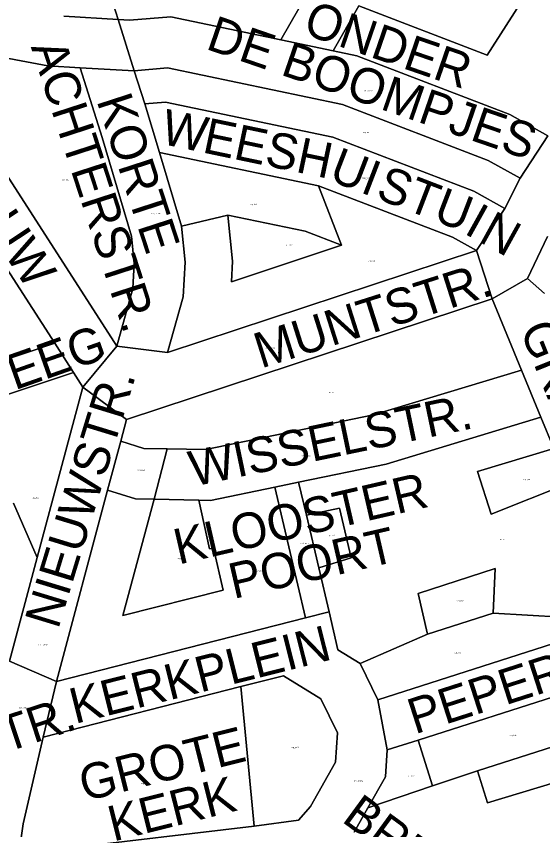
# Model space of a CAD drawing. Extents: x 14356 to 207184, y 3423 to 537581.
# Drawn here: x 132830.2 to 132986, y 517028.5 to 517269.3 of the extents above; entities that cross this region are included whole.
import ezdxf

# ---------------------------------------------------------------- set-up
doc = ezdxf.new("R2010")
doc.units = 0
for name, color, linetype in [('GEOCAD IKB VLAK TEKST CLASSIFICATIE', 7, 'Continuous'), ('PLATTEGROND ACHTERGROND BEBOUW', 7, 'Continuous'), ('PLATTEGROND ACHTERGROND GROEN', 7, 'Continuous'), ('PLATTEGROND BEBOUWING', 7, 'Continuous'), ('PLATTEGROND ERFTOEGANGSWEG', 7, 'Continuous'), ('PLATTEGROND GEB ONTSL WEG E', 7, 'Continuous'), ('PLATTEGROND HULPLIJN', 7, 'Continuous'), ('PLATTEGROND LIJN', 7, 'Continuous'), ('PLATTEGROND NAAM ERFTOEGANGSWEG', 7, 'Continuous'), ('PLATTEGROND NAAM GEB ONTSL WEG E', 7, 'Continuous'), ('PLATTEGROND VOET FIETSPAD', 7, 'Continuous'), ('PLATTEGROND WATER', 7, 'Continuous')]:
    doc.layers.add(name, color=color, linetype=linetype)

msp = doc.modelspace()

# ---------------------------------------------------------------- linework, layer by layer
at = {"layer": 'PLATTEGROND ACHTERGROND BEBOUW'}
for p, q in [((132871, 517126.31), (132884.25, 517126.05)), ((132919.7, 517106.06), (132916.05, 517121.64)), ((132971.37, 517092.61), (132951.93, 517086.38)), ((132966.69, 517045.96), (133006.29, 517058.64)), ((132939.97, 517052.1), (132949.17, 517055.05)), ((132949.17, 517055.05), (132953.43, 517041.45)), ((132953.43, 517041.45), (132934.29, 517034.94))]:
    msp.add_line(p, q, dxfattribs=at)
for points in [[(132930.4, 517308.13), (132983.31, 517279.35), (132969.62, 517257.76), (132931.54, 517272.41)], [(132926.49, 517201.5), (132893.87, 517190.73), (132894.2, 517196.86), (132892.81, 517210.43)], [(132892.81, 517210.43), (132915.69, 517205.65), (132926.49, 517201.5)], [(132993.54, 517130.99), (132970.76, 517121.87), (132966.74, 517134.52), (132989.27, 517141.37)], [(132884.25, 517126.05), (132887.35, 517111.62), (132888.55, 517111.87), (132891.46, 517099.46), (132861.78, 517091.89), (132871, 517126.31)], [(132916.05, 517121.64), (132925.85, 517123.67), (132929.3, 517108.94), (132919.7, 517106.06)], [(132951.93, 517086.38), (132949.11, 517098.39), (132971.89, 517105.87), (132971.37, 517092.61)], [(133006.29, 517058.64), (133009.49, 517048.51), (132969.65, 517036.5), (132966.69, 517045.96)], [(132934.29, 517034.94), (132939.45, 517044.13), (132939.97, 517052.1)]]:
    msp.add_lwpolyline(points, dxfattribs=at)
at = {"layer": 'PLATTEGROND ACHTERGROND GROEN'}
msp.add_line((132900.63, 517029.52), (132896.62, 517070.85), dxfattribs=at)
msp.add_lwpolyline([(132896.62, 517070.85), (132909.29, 517074.08), (132920.37, 517067.21), (132925.27, 517057.2), (132924.7, 517048.51), (132917.3, 517035.33), (132913.75, 517031.29), (132900.63, 517029.52)], dxfattribs=at)
at = {"layer": 'PLATTEGROND BEBOUWING'}
for p, q in [((132860.33, 517268.33), (132824.26, 517381.98)), ((132923.95, 517259.09), (132931.54, 517272.41)), ((132781.81, 517265.46), (132841.56, 517172.49)), ((132859.92, 517171.66), (132802.1, 517261.65)), ((132879.07, 517207.16), (132872.61, 517228.96)), ((132872.61, 517228.96), (132919.66, 517219.12)), ((132919.66, 517219.12), (132926.49, 517201.5)), ((132926.49, 517201.5), (132919.66, 517219.12)), ((132892.81, 517210.43), (132879.07, 517207.16)), ((132879.07, 517207.16), (132892.81, 517210.43)), ((132966.42, 517199.93), (132874.97, 517169.75)), ((132862.84, 517149.95), (132971.03, 517185.66)), ((132971.03, 517185.66), (132979.7, 517164.59)), ((132841.56, 517172.49), (132735.25, 517137.19)), ((132792.94, 517145.81), (132847.14, 517163.81)), ((132847.14, 517163.81), (132849.88, 517159.54)), ((132849.88, 517159.54), (132836.36, 517109.07)), ((132985.44, 517150.66), (132989.27, 517141.37)), ((132861.11, 517143.49), (132862.84, 517149.95)), ((132916.05, 517121.64), (132913.77, 517131.38)), ((132842.07, 517072.41), (132857.23, 517128.99)), ((132906.73, 517129.92), (132915.8, 517091.23)), ((132829.41, 517125.12), (132836.36, 517109.07)), ((132836.36, 517109.07), (132829.41, 517125.12)), ((132836.36, 517109.07), (132828.15, 517078.41)), ((132922.76, 517093), (132919.7, 517106.06)), ((132915.8, 517091.23), (132842.07, 517072.41)), ((133010.27, 517090.37), (132937.19, 517066.96)), ((132951.93, 517086.38), (132971.37, 517092.61)), ((133010.27, 517090.37), (132971.37, 517092.61)), ((132971.37, 517092.61), (133010.27, 517090.37)), ((132951.93, 517086.38), (132931.94, 517077.68)), ((132931.94, 517077.68), (132951.93, 517086.38)), ((132937.19, 517066.96), (132931.94, 517077.68)), ((132949.17, 517055.05), (133015.4, 517076.27)), ((132838.11, 517055.92), (132896.62, 517070.85)), ((132896.62, 517070.85), (132900.63, 517029.52)), ((133006.29, 517058.64), (132966.69, 517045.96)), ((132953.43, 517041.45), (132949.17, 517055.05)), ((132953.43, 517041.45), (132966.69, 517045.96)), ((132966.69, 517045.96), (132953.43, 517041.45)), ((132934.29, 517034.94), (132953.43, 517041.45)), ((132930.24, 517027.72), (132934.29, 517034.94)), ((132900.63, 517029.52), (132830.98, 517021.38))]:
    msp.add_line(p, q, dxfattribs=at)
for points in [[(132931.54, 517272.41), (132969.62, 517257.76), (132983.31, 517279.35), (132930.4, 517308.13)], [(132874.3, 517305.44), (132881.2, 517278.25), (132885.43, 517277.36), (132920.89, 517286.83), (132921.43, 517284.95), (132908.52, 517262.32)], [(132908.52, 517262.32), (132875.92, 517269.13), (132863.72, 517268.12), (132860.33, 517268.33)], [(132802.1, 517261.65), (132839.56, 517254.6), (132849.13, 517254)], [(132987.56, 517233.95), (132976.25, 517240.21), (132931.01, 517257.62), (132923.95, 517259.09)], [(132849.13, 517254), (132855.64, 517233.44), (132864.29, 517204.24), (132865.12, 517196.16), (132864.72, 517188.68), (132859.92, 517171.66)], [(132919.66, 517219.12), (132959.3, 517203.88), (132966.42, 517199.93)], [(132926.49, 517201.5), (132915.69, 517205.65), (132892.81, 517210.43)], [(132892.81, 517210.43), (132894.2, 517196.86), (132893.87, 517190.73), (132926.49, 517201.5)], [(132874.97, 517169.75), (132879.61, 517186.22), (132880.16, 517196.52), (132879.07, 517207.16)], [(132979.7, 517164.59), (132935.97, 517151.3), (132886.29, 517141.01), (132874.84, 517141.24)], [(132913.77, 517131.38), (132939.68, 517136.75), (132985.44, 517150.66)], [(132874.84, 517141.24), (132867.93, 517141.37), (132861.11, 517143.49)], [(132989.27, 517141.37), (132966.74, 517134.52), (132970.76, 517121.87), (132993.54, 517130.99)], [(132857.23, 517128.99), (132865.51, 517126.42), (132871, 517126.31)], [(132884.25, 517126.05), (132887.68, 517125.98), (132906.73, 517129.92)], [(132871, 517126.31), (132861.78, 517091.89), (132891.46, 517099.46), (132888.55, 517111.87), (132887.35, 517111.62), (132884.25, 517126.05)], [(132919.7, 517106.06), (132929.3, 517108.94), (132925.85, 517123.67), (132916.05, 517121.64)], [(132971.37, 517092.61), (132971.89, 517105.87), (132949.11, 517098.39), (132951.93, 517086.38)], [(132931.94, 517077.68), (132925.4, 517081.74), (132922.76, 517093)], [(132966.69, 517045.96), (132969.65, 517036.5), (133009.49, 517048.51), (133006.29, 517058.64)], [(132830.98, 517021.38), (132832.25, 517030.21), (132838.11, 517055.92)]]:
    msp.add_lwpolyline(points, dxfattribs=at)
at = {"layer": 'PLATTEGROND ERFTOEGANGSWEG'}
for p, q in [((132824.26, 517381.98), (132860.33, 517268.33)), ((132931.54, 517272.41), (132923.95, 517259.09)), ((132860.33, 517268.33), (132844.27, 517269.33)), ((132923.95, 517259.09), (132908.52, 517262.32)), ((132849.13, 517254), (132865.12, 517253.18)), ((132865.12, 517253.18), (132868.21, 517243.41)), ((132868.21, 517243.41), (132872.61, 517228.96)), ((132872.61, 517228.96), (132879.07, 517207.16)), ((132981.49, 517191.7), (132987.41, 517204.13)), ((132971.03, 517185.66), (132981.49, 517191.7)), ((132981.49, 517191.7), (132986.59, 517187.25)), ((132986.59, 517187.25), (132981.49, 517191.7)), ((132979.7, 517164.59), (132971.03, 517185.66)), ((132874.97, 517169.75), (132859.92, 517171.66)), ((132985.44, 517150.66), (132979.7, 517164.59)), ((132979.7, 517164.59), (132985.44, 517150.66)), ((132989.27, 517141.37), (132985.44, 517150.66)), ((132871, 517126.31), (132874.84, 517141.24)), ((132913.77, 517131.38), (132906.73, 517129.92)), ((132884.25, 517126.05), (132871, 517126.31)), ((132915.8, 517091.23), (132922.76, 517093)), ((132842.07, 517072.41), (132915.8, 517091.23)), ((132931.94, 517077.68), (132937.19, 517066.96)), ((132838.11, 517055.92), (132842.07, 517072.41)), ((132896.62, 517070.85), (132838.11, 517055.92)), ((132937.19, 517066.96), (132939.97, 517052.1)), ((132934.29, 517034.94), (132930.24, 517027.72)), ((132830.98, 517021.38), (132900.63, 517029.52))]:
    msp.add_line(p, q, dxfattribs=at)
for points in [[(132908.52, 517262.32), (132921.43, 517284.95), (132920.89, 517286.83), (132885.43, 517277.36), (132881.2, 517278.25), (132874.3, 517305.44)], [(132859.92, 517171.66), (132864.72, 517188.68), (132865.12, 517196.16), (132864.29, 517204.24), (132855.64, 517233.44), (132849.13, 517254)], [(132879.07, 517207.16), (132880.16, 517196.52), (132879.61, 517186.22), (132874.97, 517169.75)], [(132874.84, 517141.24), (132886.29, 517141.01), (132935.97, 517151.3), (132979.7, 517164.59)], [(132985.44, 517150.66), (132939.68, 517136.75), (132913.77, 517131.38)], [(132906.73, 517129.92), (132887.68, 517125.98), (132884.25, 517126.05)], [(132922.76, 517093), (132925.4, 517081.74), (132931.94, 517077.68)], [(132900.63, 517029.52), (132913.75, 517031.29), (132917.3, 517035.33), (132924.7, 517048.51), (132925.27, 517057.2), (132920.37, 517067.21), (132909.29, 517074.08), (132896.62, 517070.85)], [(132939.97, 517052.1), (132939.45, 517044.13), (132934.29, 517034.94)]]:
    msp.add_lwpolyline(points, dxfattribs=at)
at = {"layer": 'PLATTEGROND GEB ONTSL WEG E'}
for p, q in [((132844.27, 517269.33), (132860.33, 517268.33)), ((132865.12, 517253.18), (132860.33, 517268.33)), ((132860.33, 517268.33), (132865.12, 517253.18)), ((132841.56, 517172.49), (132781.81, 517265.46)), ((132802.1, 517261.65), (132859.92, 517171.66)), ((132908.52, 517262.32), (132923.95, 517259.09)), ((132865.12, 517253.18), (132849.13, 517254)), ((132979.34, 517221.36), (132987.56, 517233.95)), ((132987.56, 517233.95), (132979.34, 517221.36)), ((132974.8, 517212.44), (132979.34, 517221.36)), ((132966.42, 517199.93), (132974.8, 517212.44)), ((132987.41, 517204.13), (132981.49, 517191.7)), ((132874.97, 517169.75), (132966.42, 517199.93)), ((132971.03, 517185.66), (132966.42, 517199.93)), ((132966.42, 517199.93), (132971.03, 517185.66)), ((132981.49, 517191.7), (132971.03, 517185.66)), ((132971.03, 517185.66), (132862.84, 517149.95)), ((132847.14, 517163.81), (132841.56, 517172.49)), ((132859.92, 517171.66), (132849.88, 517159.54)), ((132849.88, 517159.54), (132859.92, 517171.66)), ((132859.92, 517171.66), (132874.97, 517169.75)), ((132849.88, 517159.54), (132847.14, 517163.81)), ((132836.36, 517109.07), (132849.88, 517159.54)), ((132849.88, 517159.54), (132862.84, 517149.95)), ((132862.84, 517149.95), (132849.88, 517159.54)), ((132862.84, 517149.95), (132861.11, 517143.49)), ((132861.11, 517143.49), (132857.23, 517128.99)), ((132857.23, 517128.99), (132842.07, 517072.41)), ((132828.15, 517078.41), (132836.36, 517109.07)), ((132828.15, 517078.41), (132842.07, 517072.41)), ((132842.07, 517072.41), (132828.15, 517078.41)), ((132842.07, 517072.41), (132838.11, 517055.92))]:
    msp.add_line(p, q, dxfattribs=at)
for points in [[(132860.33, 517268.33), (132863.72, 517268.12), (132875.92, 517269.13), (132908.52, 517262.32)], [(132849.13, 517254), (132839.56, 517254.6), (132802.1, 517261.65)], [(132923.95, 517259.09), (132931.01, 517257.62), (132976.25, 517240.21), (132987.56, 517233.95)], [(132979.34, 517221.36), (132969.89, 517226.59), (132926.75, 517243.18), (132874.99, 517254), (132865.12, 517253.18)], [(132838.11, 517055.92), (132832.25, 517030.21), (132830.98, 517021.38)]]:
    msp.add_lwpolyline(points, dxfattribs=at)
at = {"layer": 'PLATTEGROND HULPLIJN'}
for p, q in [((132860.33, 517268.33), (132844.27, 517269.33)), ((132865.12, 517253.18), (132860.33, 517268.33)), ((132923.95, 517259.09), (132908.52, 517262.32)), ((132849.13, 517254), (132865.12, 517253.18)), ((132872.61, 517228.96), (132868.21, 517243.41)), ((132979.34, 517221.36), (132987.56, 517233.95)), ((132926.49, 517201.5), (132919.66, 517219.12)), ((132974.8, 517212.44), (132966.42, 517199.93)), ((132892.81, 517210.43), (132879.07, 517207.16)), ((132981.49, 517191.7), (132987.41, 517204.13)), ((132966.42, 517199.93), (132971.03, 517185.66)), ((132971.03, 517185.66), (132981.49, 517191.7)), ((132981.49, 517191.7), (132986.59, 517187.25)), ((132847.14, 517163.81), (132841.56, 517172.49)), ((132849.88, 517159.54), (132859.92, 517171.66)), ((132859.92, 517171.66), (132874.97, 517169.75)), ((132979.7, 517164.59), (132985.44, 517150.66)), ((132862.84, 517149.95), (132849.88, 517159.54)), ((132861.11, 517143.49), (132857.23, 517128.99)), ((132874.84, 517141.24), (132871, 517126.31)), ((132906.73, 517129.92), (132913.77, 517131.38)), ((132829.41, 517125.12), (132836.36, 517109.07)), ((132922.76, 517093), (132915.8, 517091.23)), ((133010.27, 517090.37), (132971.37, 517092.61)), ((132951.93, 517086.38), (132931.94, 517077.68)), ((132842.07, 517072.41), (132828.15, 517078.41)), ((132838.11, 517055.92), (132842.07, 517072.41)), ((132937.19, 517066.96), (132939.97, 517052.1)), ((132953.43, 517041.45), (132966.69, 517045.96))]:
    msp.add_line(p, q, dxfattribs=at)
at = {"layer": 'PLATTEGROND LIJN'}
for p, q in [((132824.26, 517381.98), (132860.33, 517268.33)), ((132931.54, 517272.41), (132923.95, 517259.09)), ((132841.56, 517172.49), (132781.81, 517265.46)), ((132859.92, 517171.66), (132802.1, 517261.65)), ((132868.21, 517243.41), (132865.12, 517253.18)), ((132919.66, 517219.12), (132872.61, 517228.96)), ((132879.07, 517207.16), (132872.61, 517228.96)), ((132974.8, 517212.44), (132979.34, 517221.36)), ((132874.97, 517169.75), (132966.42, 517199.93)), ((132971.03, 517185.66), (132862.84, 517149.95)), ((132971.03, 517185.66), (132979.7, 517164.59)), ((132735.25, 517137.19), (132841.56, 517172.49)), ((132847.14, 517163.81), (132792.94, 517145.81)), ((132847.14, 517163.81), (132849.88, 517159.54)), ((132849.88, 517159.54), (132836.36, 517109.07)), ((132989.27, 517141.37), (132985.44, 517150.66)), ((132862.84, 517149.95), (132861.11, 517143.49)), ((132913.77, 517131.38), (132916.05, 517121.64)), ((132842.07, 517072.41), (132857.23, 517128.99)), ((132906.73, 517129.92), (132915.8, 517091.23)), ((132871, 517126.31), (132884.25, 517126.05)), ((132916.05, 517121.64), (132919.7, 517106.06)), ((132836.36, 517109.07), (132828.15, 517078.41)), ((132919.7, 517106.06), (132922.76, 517093)), ((132915.8, 517091.23), (132842.07, 517072.41)), ((132937.19, 517066.96), (133010.27, 517090.37)), ((132971.37, 517092.61), (132951.93, 517086.38)), ((132937.19, 517066.96), (132931.94, 517077.68)), ((132949.17, 517055.05), (133015.4, 517076.27)), ((132838.11, 517055.92), (132896.62, 517070.85)), ((132896.62, 517070.85), (132900.63, 517029.52)), ((133006.29, 517058.64), (132966.69, 517045.96)), ((132949.17, 517055.05), (132939.97, 517052.1)), ((132949.17, 517055.05), (132953.43, 517041.45)), ((132953.43, 517041.45), (132934.29, 517034.94)), ((132930.24, 517027.72), (132934.29, 517034.94)), ((132900.63, 517029.52), (132830.98, 517021.38))]:
    msp.add_line(p, q, dxfattribs=at)
for points in [[(132931.54, 517272.41), (132969.62, 517257.76), (132983.31, 517279.35), (132930.4, 517308.13)], [(132908.52, 517262.32), (132921.43, 517284.95), (132920.89, 517286.83), (132885.43, 517277.36), (132881.2, 517278.25), (132874.3, 517305.44)], [(132860.33, 517268.33), (132863.72, 517268.12), (132875.92, 517269.13), (132908.52, 517262.32)], [(132802.1, 517261.65), (132839.56, 517254.6), (132849.13, 517254)], [(132987.56, 517233.95), (132976.25, 517240.21), (132931.01, 517257.62), (132923.95, 517259.09)], [(132849.13, 517254), (132855.64, 517233.44), (132864.29, 517204.24), (132865.12, 517196.16), (132864.72, 517188.68), (132859.92, 517171.66)], [(132979.34, 517221.36), (132969.89, 517226.59), (132926.75, 517243.18), (132874.99, 517254), (132865.12, 517253.18)], [(132974.8, 517212.44), (132965.66, 517217.5), (132923.92, 517233.56), (132874.37, 517243.92), (132868.21, 517243.41)], [(132966.42, 517199.93), (132959.3, 517203.88), (132919.66, 517219.12)], [(132892.81, 517210.43), (132894.2, 517196.86), (132893.87, 517190.73), (132926.49, 517201.5)], [(132926.49, 517201.5), (132915.69, 517205.65), (132892.81, 517210.43)], [(132874.97, 517169.75), (132879.61, 517186.22), (132880.16, 517196.52), (132879.07, 517207.16)], [(132979.7, 517164.59), (132935.97, 517151.3), (132886.29, 517141.01), (132874.84, 517141.24)], [(132985.44, 517150.66), (132939.68, 517136.75), (132913.77, 517131.38)], [(132874.84, 517141.24), (132867.93, 517141.37), (132861.11, 517143.49)], [(132989.27, 517141.37), (132966.74, 517134.52), (132970.76, 517121.87), (132993.54, 517130.99)], [(132857.23, 517128.99), (132865.51, 517126.42), (132871, 517126.31)], [(132884.25, 517126.05), (132887.68, 517125.98), (132906.73, 517129.92)], [(132871, 517126.31), (132861.78, 517091.89), (132891.46, 517099.46), (132888.55, 517111.87), (132887.35, 517111.62), (132884.25, 517126.05)], [(132919.7, 517106.06), (132929.3, 517108.94), (132925.85, 517123.67), (132916.05, 517121.64)], [(132951.93, 517086.38), (132949.11, 517098.39), (132971.89, 517105.87), (132971.37, 517092.61)], [(132931.94, 517077.68), (132925.4, 517081.74), (132922.76, 517093)], [(132896.62, 517070.85), (132909.29, 517074.08), (132920.37, 517067.21), (132925.27, 517057.2), (132924.7, 517048.51), (132917.3, 517035.33), (132913.75, 517031.29), (132900.63, 517029.52)], [(132966.69, 517045.96), (132969.65, 517036.5), (133009.49, 517048.51), (133006.29, 517058.64)], [(132830.98, 517021.38), (132832.25, 517030.21), (132838.11, 517055.92)], [(132939.97, 517052.1), (132939.45, 517044.13), (132934.29, 517034.94)]]:
    msp.add_lwpolyline(points, dxfattribs=at)
at = {"layer": 'PLATTEGROND VOET FIETSPAD'}
for p, q in [((132872.61, 517228.96), (132868.21, 517243.41)), ((132919.66, 517219.12), (132872.61, 517228.96)), ((132974.8, 517212.44), (132966.42, 517199.93)), ((132735.25, 517137.19), (132841.56, 517172.49)), ((132841.56, 517172.49), (132847.14, 517163.81)), ((132847.14, 517163.81), (132792.94, 517145.81)), ((132857.23, 517128.99), (132861.11, 517143.49)), ((132874.84, 517141.24), (132871, 517126.31)), ((132906.73, 517129.92), (132913.77, 517131.38)), ((132913.77, 517131.38), (132916.05, 517121.64)), ((132915.8, 517091.23), (132906.73, 517129.92)), ((132916.05, 517121.64), (132919.7, 517106.06)), ((132919.7, 517106.06), (132922.76, 517093)), ((132922.76, 517093), (132915.8, 517091.23)), ((132937.19, 517066.96), (133010.27, 517090.37)), ((133015.4, 517076.27), (132949.17, 517055.05)), ((132939.97, 517052.1), (132937.19, 517066.96)), ((132949.17, 517055.05), (132939.97, 517052.1))]:
    msp.add_line(p, q, dxfattribs=at)
for points in [[(132868.21, 517243.41), (132874.37, 517243.92), (132923.92, 517233.56), (132965.66, 517217.5), (132974.8, 517212.44)], [(132966.42, 517199.93), (132959.3, 517203.88), (132919.66, 517219.12)], [(132861.11, 517143.49), (132867.93, 517141.37), (132874.84, 517141.24)], [(132871, 517126.31), (132865.51, 517126.42), (132857.23, 517128.99)]]:
    msp.add_lwpolyline(points, dxfattribs=at)
at = {"layer": 'PLATTEGROND WATER'}
for p, q in [((132868.21, 517243.41), (132865.12, 517253.18)), ((132979.34, 517221.36), (132974.8, 517212.44))]:
    msp.add_line(p, q, dxfattribs=at)
for points in [[(132865.12, 517253.18), (132874.99, 517254), (132926.75, 517243.18), (132969.89, 517226.59), (132979.34, 517221.36)], [(132974.8, 517212.44), (132965.66, 517217.5), (132923.92, 517233.56), (132874.37, 517243.92), (132868.21, 517243.41)]]:
    msp.add_lwpolyline(points, dxfattribs=at)

# ---------------------------------------------------------------- texts
at = {"layer": 'GEOCAD IKB VLAK TEKST CLASSIFICATIE'}
for s, p in [('CPG_WEGE', (132933.07, 517247.05)), ('cpg_wtr', (132932.9, 517234.77)), ('cpg_bw1', (132843.82, 517220.76)), ('CPG_PAD', (132932.55, 517221.17)), ('cpg_bw1', (132899.49, 517213.44)), ('CPG_ERFW', (132870.15, 517210.73)), ('cpg_grn2', (132909.98, 517201.47)), ('cpg_bw1', (132934.5, 517196.65)), ('CPG_WEGE', (132903.96, 517171.02)), ('cpg_bw1', (132922.53, 517157.85)), ('CPG_ERFW', (132914.63, 517138.96)), ('CPG_PAD', (132865.99, 517134.7)), ('cpg_grn2', (132980.29, 517132.01)), ('cpg_bw1', (132834.99, 517126.63)), ('cpg_grn2', (132922.6, 517115.5)), ('cpg_bw1', (132973.14, 517114.33)), ('CPG_PAD', (132914.34, 517113.07)), ('cpg_grn2', (132877.79, 517108.65)), ('cpg_bw1', (132901.37, 517104.87)), ('cpg_grn2', (132960.56, 517096.1)), ('CPG_WEGE', (132836.72, 517083.05)), ('cpg_bw1', (132959.93, 517080.74)), ('CPG_PAD', (132969.99, 517069.47)), ('CPG_WEGE', (132831.01, 517064.33)), ('cpg_bw1', (132976.25, 517056.25)), ('cpg_grn3', (132911.68, 517052.71)), ('cpg_grn2', (132945.99, 517044.26)), ('cpg_bw1', (132867.19, 517042.04)), ('CPG_ERFW', (132930.13, 517042.73))]:
    msp.add_text(s, height=0.35, dxfattribs=at).set_placement(p)
at = {"layer": 'PLATTEGROND NAAM ERFTOEGANGSWEG'}
for s, rotation, p in [('ACHTERSTR.', 288, (132834.45, 517260.27)), ('KORTE', 288, (132853.9, 517244.38)), ('W', 348.19, (132872.57, 517231.65)), ('E', 348.19, (132884.96, 517229.06)), ('E', 348.19, (132894.16, 517227.14)), ('S', 348.19, (132903.37, 517225.21)), ('H', 348.19, (132912.58, 517223.29)), ('U', 338.9611, (132922.32, 517220.91)), ('I', 338.9611, (132931.7, 517217.3)), ('S', 338.9611, (132936.22, 517215.57)), ('T', 338.9611, (132944.99, 517212.19)), ('U', 338.9611, (132953.16, 517209.05)), ('I', 331.035, (132962.4, 517205.16)), ('N', 331.035, (132966.63, 517202.82)), ('NIEUWSTEEG', 19.3835, (132768.66, 517137.05)), ('GRAVENSTR.', 291.9493, (132979.15, 517176.7)), ('WISSELSTR.', 11.7795, (132882.6, 517130.05)), ('KLOOSTER', 13, (132878.22, 517106.96)), ('POORT', 13, (132894.52, 517096.78)), ('KERKPLEIN', 14.0871, (132847.55, 517059.78)), ('PEPERSTR.', 17.8196, (132948.18, 517056.69)), ('LANGE KERKSTR.', 18.2632, (132733.07, 517020.26)), ('GROTE', 14.0871, (132850.38, 517036.82)), ('KERK', 14.0871, (132858.9, 517024.94)), ('BREE', 323.8786, (132926.19, 517031.08))]:
    msp.add_text(s, height=10.5, rotation=rotation, dxfattribs=at).set_placement(p)
at = {"layer": 'PLATTEGROND NAAM GEB ONTSL WEG E'}
for s, rotation, p in [('ONDER', 341, (132914.69, 517264.22)), ('DE BOOMPJES', 341, (132885.96, 517259.74)), ('GOUW', 303.5798, (132808.69, 517225.7)), ('MUNTSTR.', 17.5991, (132902.64, 517164.99)), ('NIEUWSTR.', 72.995, (132842.59, 517087.6))]:
    msp.add_text(s, height=10.5, rotation=rotation, dxfattribs=at).set_placement(p)

doc.saveas('drawing.dxf')
